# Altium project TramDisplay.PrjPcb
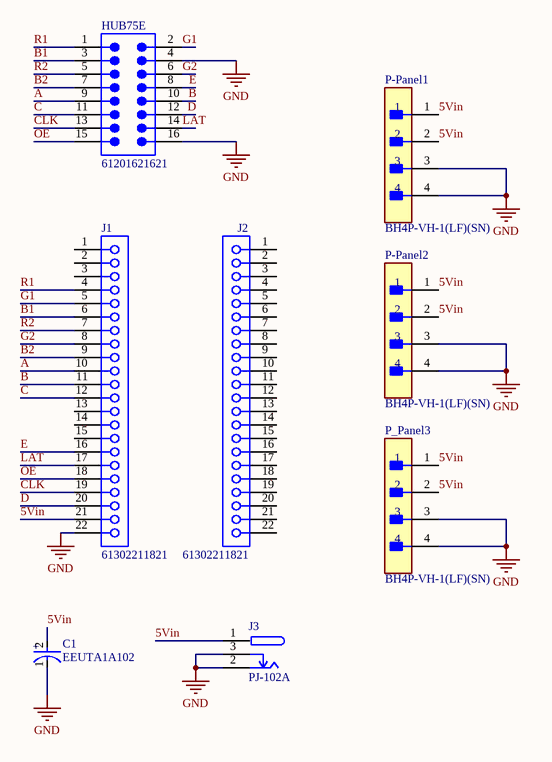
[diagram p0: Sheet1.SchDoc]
1 sheet, 8 parts. Net scope: global (net labels, ports and power ports of the same name join across sheets).
Board file: PCB1.PcbDoc

## Sheet Sheet1.SchDoc
size A4; SheetNumber: 1; SheetTotal: 1

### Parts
C1  EEUTA1A102  [FP-RAD-TH-D_10_0_5-L_20_2-MFG]
HUB75E  61201621621  [61201621621]
J1  61302211821  [61302211821]
J2  61302211821  [61302211821]
J3  PJ-102A  [FP-PJ-102A-MFG]
P-Panel1  BH4P-VH-1(LF)(SN)  [FP-BH4P-VH-1_LF_SN-MFG]
P-Panel2  BH4P-VH-1(LF)(SN)  [FP-BH4P-VH-1_LF_SN-MFG]
P_Panel3  BH4P-VH-1(LF)(SN)  [FP-BH4P-VH-1_LF_SN-MFG]

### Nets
GND: C1.1(C) HUB75E.4 HUB75E.16 J1.22 J3.2 J3.3 P-Panel1.3 P-Panel1.4 P-Panel2.3 P-Panel2.4 P_Panel3.3 P_Panel3.4
5Vin: C1.2(A) J1.21 J3.1 P-Panel1.1 P-Panel1.2 P-Panel2.1 P-Panel2.2 P_Panel3.1 P_Panel3.2
A: HUB75E.9 J1.10
B: HUB75E.10 J1.11
B1: HUB75E.3 J1.6
B2: HUB75E.7 J1.9
C: HUB75E.11 J1.12
CLK: HUB75E.13 J1.19
D: HUB75E.12 J1.20
E: HUB75E.8 J1.16
G1: HUB75E.2 J1.5
G2: HUB75E.6 J1.8
LAT: HUB75E.14 J1.17
OE: HUB75E.15 J1.18
R1: HUB75E.1 J1.4
R2: HUB75E.5 J1.7

Not connected (* = marked no-connect by the designer): J1 1 2 3 13 14 15; J2 1 2 3 4 5 6 7 8 9 10 11 12 13 14 15 16 17 18 19 20 21 22

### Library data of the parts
C1 = CMP-05427-000150-1: Aluminum Electrolytic Capacitors (Radial Lead Type) AEC-Q200 Qualified 1000uF ±20% 10V; Life (Hours): 2000Hour; Impedance: 57mR; Ripple Current: 1.1A; Capacitance: 1mF; Lead Diameter: 0.6mm
HUB75E = CMP-1502-00009-3: WR-BHD Straight Male, Box Header, Through Hole, 2 Rows, 16 Contacts, 2.54mm Pitch; Insulation: Insulated; Number of Contacts: 16; Voltage Rating: 250V; Current Rating: 3A; Connector Type: Male Pin; Insulation Resistance: 1GΩ; Contact Resistance: 20mΩ
J1 J2 = CMP-1502-01352-4: Btb Conn, Rcpt, 22Pos, 1Row, 2.54Mm Rohs Compliant: Yes; Contact Resistance: 20mΩ; Operating Supply Voltage: 250V; Current Rating: 3A; Gender: Female
J3 = CMP-12637-106234071-1: PJ-102A 2.0 x 6.5 mm, 2.5 A, Horizontal, Through Hole, Tapered Pins, Dc Power Jack Connector; Voltage Rating (DC): 24V; Number of Contacts: 3; Outside Diameter: 6.5mm; Gender: Male; Shielding: No; Insulation Resistance: 50MΩ; Current Rating: 2.5A; Inside Diameter: 2mm; Number of Conductors: 2
P-Panel1 P-Panel2 P_Panel3 = CMP-17439-000652-1: VH Series 4 Position 3.96 mm Pitch Through Hole Shrouded Header; Pitch: 3.96mm; Number of Positions: 4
